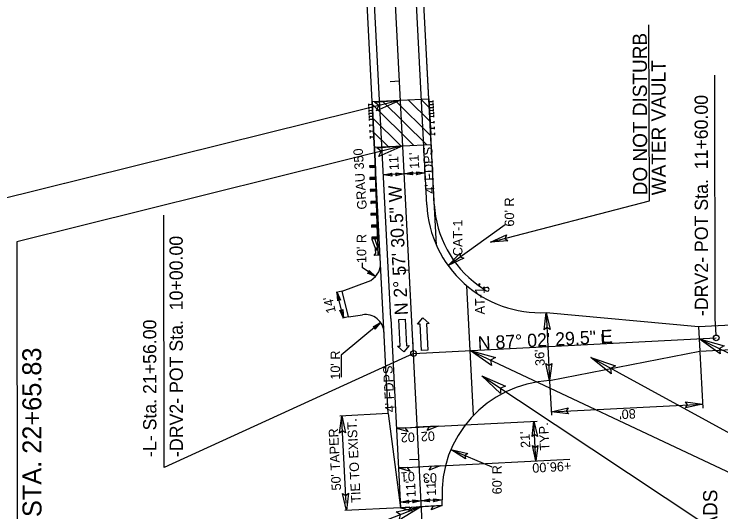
# Model space of a CAD drawing. Extents: x 1373164 to 1374172, y 550391 to 553180.
# Drawn here: x 1373512.6 to 1373885.8, y 551435.1 to 551698 of the extents above; entities that cross this region are included whole.
import ezdxf

# ---------------------------------------------------------------- set-up
doc = ezdxf.new("R2010")
doc.units = 0
for name, color, linetype in [('Default Symbol Cogo Elevation', 7, 'Continuous'), ('Exist Building Cogo Elevation', 7, 'Continuous'), ('Exist Building Cogo Number', 7, 'Continuous'), ('Exist Building Cogo Point CELL', 7, 'Continuous'), ('Exist Other Culture Fence Line Cogo Comment', 7, 'Continuous'), ('Exist Other Culture Fence Line Cogo Elevation', 7, 'Continuous'), ('Exist Other Culture Fence Line Cogo Point CELL', 7, 'Continuous'), ('Exist Other Culture Gate Cogo Comment', 7, 'Continuous'), ('Exist Other Culture Gate Cogo Elevation', 7, 'Continuous'), ('Exist Other Culture Gate Cogo Number', 7, 'Continuous'), ('Exist Other Culture Gate Cogo Point CELL', 7, 'Continuous'), ('Exist Roads EOP Other Cogo Comment', 7, 'Continuous'), ('Exist Roads EOP Other Cogo Elevation', 7, 'Continuous'), ('Exist Structure Major Deck Tunnel Box Culvert Cogo Number', 7, 'Continuous'), ('Exist Structure Major Deck Tunnel Box Culvert Cogo Point CELL', 7, 'Continuous'), ('Exist Structure Minor Pipes RCP 18 Inch Cogo Comment', 7, 'Continuous'), ('Exist Structure Minor Pipes RCP 18 Inch Cogo Number', 7, 'Continuous'), ('Exist Utilities Sanitary Sewer Manhole Cogo Elevation', 7, 'Continuous'), ('Exist Utilities Sanitary Sewer Manhole Cogo Number', 7, 'Continuous')]:
    doc.layers.add(name, color=color, linetype=linetype)

msp = doc.modelspace()

# ---------------------------------------------------------------- linework, layer by layer
at = {"layer": 'Default Symbol Cogo Elevation'}
for p, q in [((1373711.58, 551537.14), (1373696.04, 551837.8)), ((1373730.5, 551597.19), (1373718.01, 551838.94)), ((1373685.75, 551551.68), (1373699.49, 551556.7)), ((1373755.27, 551486.13), (1373751.74, 551554.43)), ((1373689.13, 551538.17), (1373685.75, 551551.68)), ((1373689.14, 551538.16), (1373696.54, 551539.22)), ((1373793.52, 551540.37), (1373874.01, 551533.02)), ((1373711.58, 551537.14), (1373716.7, 551437.27)), ((1373874.01, 551533.02), (1373874.68, 551520.03)), ((1373795.38, 551504.42), (1373874.68, 551520.03)), ((1373716.7, 551437.27), (1373727.72, 551437.84)), ((1373727.72, 551437.84), (1373738.71, 551438.41)), ((1373738.71, 551438.41), (1373738.56, 551441.4))]:
    msp.add_line(p, q, dxfattribs=at)
for centre, radius, start, end in [((1373790.42, 551600.29), 60, 182.9585, 272.9585), ((1373696.06, 551566.09), 10, 290.0644, 2.9585), ((1373697.96, 551529.32), 10, 2.9585, 98.1594), ((1373798.48, 551444.5), 60, 92.9585, 182.9585)]:
    msp.add_arc(centre, radius, start, end, dxfattribs=at)
at = {"layer": 'Exist Building Cogo Elevation'}
for p, q in [((1373702.62, 551633.05), (1373701.65, 551651.78)), ((1373732.58, 551634.6), (1373731.61, 551653.33)), ((1373703.26, 551620.57), (1373702.62, 551633.05)), ((1373733.22, 551622.12), (1373732.58, 551634.6)), ((1373704.84, 551570.58), (1373703.26, 551620.57))]:
    msp.add_line(p, q, dxfattribs=at)
at = {"layer": 'Exist Building Cogo Number'}
for p, q in [((1373710.16, 551487), (1373692.04, 551837.6)), ((1373735.61, 551575.89), (1373722, 551839.14)), ((1373710.16, 551487), (1373716.7, 551437.27))]:
    msp.add_line(p, q, dxfattribs=at)
at = {"layer": 'Exist Building Cogo Point CELL'}
for p, q in [((1373716.11, 551662.54), (1373711.12, 551662.28)), ((1373721.27, 551562.67), (1373716.28, 551562.41)), ((1373823.41, 551523.89), (1373823.15, 551528.89)), ((1373726.43, 551462.81), (1373721.44, 551462.55))]:
    msp.add_line(p, q, dxfattribs=at)
at = {"layer": 'Exist Other Culture Fence Line Cogo Comment'}
for p, q in [((1373702.9, 551627.64), (1373701.65, 551651.78)), ((1373730.28, 551629.06), (1373707.15, 551652.06)), ((1373732.62, 551633.79), (1373713.89, 551652.41)), ((1373732.23, 551641.22), (1373720.63, 551652.76)), ((1373731.85, 551648.65), (1373727.37, 551653.11)), ((1373732.86, 551629.19), (1373731.61, 551653.33)), ((1373723.54, 551628.71), (1373701.72, 551650.41)), ((1373716.8, 551628.36), (1373702.1, 551642.98)), ((1373710.06, 551628.01), (1373702.49, 551635.55)), ((1373702.9, 551627.64), (1373732.86, 551629.19)), ((1373703.32, 551627.66), (1373702.87, 551628.11))]:
    msp.add_line(p, q, dxfattribs=at)
at = {"layer": 'Exist Other Culture Fence Line Cogo Elevation'}
for p, q in [((1373701.65, 551651.78), (1373695.3, 551774.61)), ((1373731.61, 551653.33), (1373725.26, 551776.16)), ((1373701.65, 551651.78), (1373731.61, 551653.33))]:
    msp.add_line(p, q, dxfattribs=at)
at = {"layer": 'Exist Other Culture Fence Line Cogo Point CELL'}
for p, q in [((1373714.57, 551479.22), (1373726.56, 551479.83)), ((1373736.54, 551480.35), (1373724.56, 551479.73)), ((1373715.7, 551458.25), (1373726.64, 551458.81)), ((1373737.63, 551459.38), (1373725.64, 551458.76)), ((1373716.7, 551437.27), (1373728.68, 551437.89)), ((1373738.71, 551438.41), (1373726.73, 551437.79))]:
    msp.add_line(p, q, dxfattribs=at)
for points in [[(1373714.57, 551479.22), (1373720.67, 551477.53), (1373719.19, 551479.45)], [(1373736.54, 551480.35), (1373730.65, 551478.04), (1373731.92, 551480.11)], [(1373715.7, 551458.25), (1373721.8, 551456.56), (1373720.32, 551458.48)], [(1373737.63, 551459.38), (1373731.74, 551457.07), (1373733.01, 551459.14)], [(1373738.71, 551438.41), (1373732.82, 551436.1), (1373734.09, 551438.17)], [(1373716.7, 551437.27), (1373722.79, 551435.58), (1373721.31, 551437.51)]]:
    msp.add_lwpolyline(points, close=True, dxfattribs=at)
at = {"layer": 'Exist Other Culture Gate Cogo Comment'}
for p, q in [((1373703.34, 551618.03), (1373700.34, 551617.93)), ((1373701.87, 551616.98), (1373700.34, 551617.93)), ((1373700.34, 551617.93), (1373700.37, 551616.93)), ((1373700.37, 551616.93), (1373701.84, 551617.98)), ((1373703.37, 551617.03), (1373700.37, 551616.93)), ((1373701.84, 551617.98), (1373701.87, 551616.98)), ((1373701.84, 551617.98), (1373703.37, 551617.03)), ((1373701.87, 551616.98), (1373703.34, 551618.03)), ((1373703.37, 551617.03), (1373701.87, 551616.98)), ((1373703.26, 551620.57), (1373704.74, 551573.84)), ((1373703.34, 551618.03), (1373703.37, 551617.03)), ((1373703.54, 551611.73), (1373700.49, 551611.63)), ((1373702.05, 551610.68), (1373700.49, 551611.63)), ((1373700.49, 551611.63), (1373700.52, 551610.63)), ((1373700.52, 551610.63), (1373702.02, 551611.68)), ((1373703.57, 551610.73), (1373700.52, 551610.63)), ((1373702.02, 551611.68), (1373702.05, 551610.68)), ((1373702.02, 551611.68), (1373703.57, 551610.73)), ((1373703.54, 551611.73), (1373702.05, 551610.68)), ((1373703.74, 551605.43), (1373700.69, 551605.34)), ((1373702.25, 551604.38), (1373700.69, 551605.34)), ((1373700.69, 551605.34), (1373700.73, 551604.34)), ((1373700.73, 551604.34), (1373702.22, 551605.38)), ((1373703.77, 551604.43), (1373700.73, 551604.34)), ((1373702.22, 551605.38), (1373702.25, 551604.38)), ((1373702.22, 551605.38), (1373703.77, 551604.43)), ((1373703.74, 551605.43), (1373702.25, 551604.38)), ((1373703.94, 551599.13), (1373700.91, 551599.04)), ((1373702.45, 551598.09), (1373700.91, 551599.04)), ((1373700.91, 551599.04), (1373700.94, 551598.04)), ((1373700.94, 551598.04), (1373702.42, 551599.09)), ((1373702.42, 551599.09), (1373702.45, 551598.09)), ((1373702.42, 551599.09), (1373703.97, 551598.13)), ((1373703.94, 551599.13), (1373702.45, 551598.09)), ((1373703.94, 551599.13), (1373703.97, 551598.13)), ((1373703.97, 551598.13), (1373700.94, 551598.04)), ((1373704.14, 551592.84), (1373701, 551592.74)), ((1373702.6, 551591.79), (1373701, 551592.74)), ((1373701, 551592.74), (1373701.03, 551591.74)), ((1373701.03, 551591.74), (1373702.57, 551592.79)), ((1373704.17, 551591.84), (1373701.03, 551591.74)), ((1373702.57, 551592.79), (1373702.6, 551591.79)), ((1373702.57, 551592.79), (1373704.17, 551591.84)), ((1373704.14, 551592.84), (1373702.6, 551591.79)), ((1373704.34, 551586.54), (1373701.34, 551586.44)), ((1373702.87, 551585.49), (1373701.34, 551586.44)), ((1373701.34, 551586.44), (1373701.37, 551585.44)), ((1373701.37, 551585.44), (1373702.84, 551586.49)), ((1373704.37, 551585.54), (1373701.37, 551585.44)), ((1373702.84, 551586.49), (1373702.87, 551585.49)), ((1373702.84, 551586.49), (1373704.37, 551585.54)), ((1373704.34, 551586.54), (1373702.87, 551585.49)), ((1373704.54, 551580.24), (1373701.48, 551580.14)), ((1373703.04, 551579.19), (1373701.48, 551580.14)), ((1373701.48, 551580.14), (1373701.51, 551579.14)), ((1373701.51, 551579.14), (1373703.01, 551580.19)), ((1373703.01, 551580.19), (1373703.04, 551579.19)), ((1373703.01, 551580.19), (1373704.57, 551579.24)), ((1373704.54, 551580.24), (1373703.04, 551579.19)), ((1373704.57, 551579.24), (1373701.51, 551579.14)), ((1373701.51, 551579.14), (1373703.22, 551574.29)), ((1373703.04, 551579.19), (1373704.72, 551574.34)), ((1373704.72, 551574.34), (1373703.22, 551574.29)), ((1373703.22, 551574.29), (1373703.24, 551573.79)), ((1373704.76, 551573.34), (1373703.22, 551574.29)), ((1373703.22, 551574.29), (1373703.26, 551573.29)), ((1373703.26, 551573.29), (1373704.72, 551574.34)), ((1373704.76, 551573.34), (1373703.26, 551573.29)), ((1373703.44, 551573.75), (1373704.06, 551573.78)), ((1373703.55, 551571.7), (1373703.44, 551573.75)), ((1373704.06, 551573.78), (1373704.67, 551573.81)), ((1373704.67, 551573.81), (1373704.77, 551571.76)), ((1373702.75, 551570.48), (1373703.55, 551571.7)), ((1373705.69, 551570.63), (1373702.75, 551570.48)), ((1373704.77, 551571.76), (1373705.69, 551570.63)), ((1373758.11, 551555.54), (1373757.64, 551554.89)), ((1373757.64, 551554.89), (1373758.68, 551555.13)), ((1373757.64, 551554.89), (1373760.51, 551552.81)), ((1373757.64, 551554.89), (1373758.21, 551554.48)), ((1373758.68, 551555.13), (1373758.11, 551555.54)), ((1373758.21, 551554.48), (1373758.11, 551555.54)), ((1373758.21, 551554.48), (1373758.68, 551555.13)), ((1373760.58, 551553.76), (1373760.1, 551553.1)), ((1373761.14, 551553.35), (1373760.58, 551553.76)), ((1373760.67, 551552.69), (1373760.58, 551553.76)), ((1373762.19, 551553.55), (1373761.03, 551553.19)), ((1373760.1, 551553.1), (1373761.14, 551553.35)), ((1373760.1, 551553.1), (1373760.67, 551552.69)), ((1373760.56, 551552.77), (1373760.45, 551552.85)), ((1373760.56, 551552.77), (1373760.45, 551552.85)), ((1373760.51, 551552.81), (1373761.9, 551551.8)), ((1373760.67, 551552.69), (1373761.14, 551553.35)), ((1373760.67, 551552.69), (1373760.88, 551552.98)), ((1373760.67, 551552.69), (1373760.88, 551552.98))]:
    msp.add_line(p, q, dxfattribs=at)
msp.add_ellipse((1373762.48, 551552.61), major_axis=(0.583, 0.804), ratio=0.995379, start_param=3.141593, end_param=7.214552, dxfattribs=at)
at = {"layer": 'Exist Other Culture Gate Cogo Elevation'}
for p, q in [((1373699.7, 551650.69), (1373699.76, 551649.54)), ((1373701.65, 551651.78), (1373702.62, 551633.05)), ((1373731.61, 551653.33), (1373732.58, 551634.6)), ((1373731.69, 551651.77), (1373733.69, 551651.87)), ((1373733.66, 551652.44), (1373733.72, 551651.3)), ((1373733.74, 551650.88), (1373733.8, 551649.74)), ((1373701.73, 551650.22), (1373699.73, 551650.11)), ((1373699.78, 551649.13), (1373699.84, 551647.98)), ((1373701.81, 551648.66), (1373699.81, 551648.55)), ((1373699.86, 551647.57), (1373699.92, 551646.42)), ((1373701.89, 551647.1), (1373699.89, 551646.99)), ((1373731.77, 551650.21), (1373733.77, 551650.31)), ((1373731.85, 551648.65), (1373733.85, 551648.75)), ((1373731.93, 551647.08), (1373733.93, 551647.19)), ((1373733.82, 551649.32), (1373733.88, 551648.18)), ((1373733.9, 551647.76), (1373733.96, 551646.62)), ((1373699.94, 551646.01), (1373700, 551644.86)), ((1373701.97, 551645.54), (1373699.97, 551645.43)), ((1373700.02, 551644.44), (1373700.08, 551643.3)), ((1373702.05, 551643.98), (1373700.05, 551643.87)), ((1373732.01, 551645.52), (1373734.01, 551645.63)), ((1373732.09, 551643.96), (1373734.09, 551644.07)), ((1373733.98, 551646.2), (1373734.04, 551645.06)), ((1373734.06, 551644.64), (1373734.12, 551643.5)), ((1373700.11, 551642.88), (1373700.16, 551641.74)), ((1373702.13, 551642.42), (1373700.13, 551642.31)), ((1373700.27, 551639.76), (1373700.33, 551638.62)), ((1373732.25, 551640.84), (1373734.25, 551640.95)), ((1373734.22, 551641.52), (1373734.28, 551640.37)), ((1373702.29, 551639.29), (1373700.3, 551639.19)), ((1373700.43, 551636.64), (1373700.49, 551635.5)), ((1373702.45, 551636.17), (1373700.46, 551636.07)), ((1373732.41, 551637.72), (1373734.41, 551637.83)), ((1373734.38, 551638.4), (1373734.44, 551637.25)), ((1373700.59, 551633.52), (1373700.65, 551632.38)), ((1373702.62, 551633.05), (1373700.62, 551632.95)), ((1373732.58, 551634.6), (1373734.57, 551634.7)), ((1373734.54, 551635.28), (1373734.6, 551634.13))]:
    msp.add_line(p, q, dxfattribs=at)
at = {"layer": 'Exist Other Culture Gate Cogo Number'}
for p, q in [((1373702.62, 551633.05), (1373703.26, 551620.57)), ((1373734.5, 551597.4), (1373732.58, 551634.6))]:
    msp.add_line(p, q, dxfattribs=at)
msp.add_arc((1373790.42, 551600.29), 56, 182.9585, 234.1663, dxfattribs=at)
at = {"layer": 'Exist Other Culture Gate Cogo Point CELL'}
msp.add_line((1373714.57, 551479.22), (1373736.54, 551480.35), dxfattribs=at)
at = {"layer": 'Exist Roads EOP Other Cogo Elevation'}
for p, q in [((1373734.13, 551313.82), (1373707.02, 551838.37)), ((1373723.54, 551518.73), (1373883.33, 551526.99))]:
    msp.add_line(p, q, dxfattribs=at)
at = {"layer": 'Exist Structure Major Deck Tunnel Box Culvert Cogo Point CELL'}
for points in [[(1373702.97, 551651.56), (1373716.63, 551652.55), (1373704.03, 551646.95), (1373705.13, 551649.7)], [(1373704.21, 551627.42), (1373717.88, 551628.41), (1373705.28, 551622.81), (1373706.37, 551625.56)], [(1373712.17, 551612.49), (1373707.63, 551613.04), (1373712.11, 551614.07), (1373711.58, 551613.24)], [(1373714.11, 551614.15), (1373718.64, 551613.61), (1373714.16, 551612.57), (1373714.7, 551613.4)], [(1373723.17, 551613.06), (1373718.64, 551613.61), (1373723.12, 551614.64), (1373722.59, 551613.81)], [(1373725.09, 551614.71), (1373729.63, 551614.17), (1373725.15, 551613.14), (1373725.68, 551613.97)], [(1373773.28, 551578.28), (1373764.18, 551577.52), (1373772.54, 551581.34), (1373771.83, 551579.51)], [(1373750, 551569.16), (1373741.79, 551565.15), (1373748.19, 551571.74), (1373748.2, 551569.77)], [(1373700.18, 551562.55), (1373703.51, 551559.42), (1373699.3, 551561.25), (1373700.22, 551561.6)], [(1373683.47, 551546.47), (1373683.13, 551551.02), (1373685, 551546.83), (1373684.08, 551547.19)], [(1373686.18, 551542), (1373686.52, 551537.44), (1373684.65, 551541.64), (1373685.56, 551541.27)], [(1373792.44, 551531.3), (1373793.52, 551540.37), (1373795.59, 551531.42), (1373793.93, 551532.48)], [(1373702.13, 551532.82), (1373706.09, 551535.09), (1373703.11, 551531.59), (1373703.04, 551532.57)], [(1373885.47, 551518.53), (1373874.34, 551526.52), (1373887.6, 551522.75), (1373885, 551521.34)], [(1373764.72, 551512.42), (1373753.5, 551520.28), (1373766.81, 551516.66), (1373764.22, 551515.22)], [(1373827.85, 551508.02), (1373817.12, 551516.54), (1373830.18, 551512.13), (1373827.52, 551510.85)], [(1373796.46, 551513.49), (1373795.38, 551504.42), (1373793.31, 551513.37), (1373794.97, 551512.31)], [(1373769.46, 551497.57), (1373759.5, 551506.97), (1373772.14, 551501.46), (1373769.37, 551500.42)], [(1373867.06, 551493.12), (1373876.13, 551492.03), (1373867.17, 551489.97), (1373868.24, 551491.63)], [(1373805.3, 551486.82), (1373796.23, 551487.9), (1373805.19, 551489.97), (1373804.12, 551488.31)], [(1373684.5, 551476.66), (1373685.59, 551485.73), (1373687.65, 551476.77), (1373685.99, 551477.84)], [(1373786.13, 551474.8), (1373787.1, 551482.96), (1373788.96, 551474.9), (1373787.47, 551475.86)], [(1373750.94, 551463.04), (1373743.27, 551467.99), (1373752.22, 551465.92), (1373750.53, 551464.9)], [(1373789.16, 551470.15), (1373788.18, 551461.99), (1373786.33, 551470.05), (1373787.82, 551469.09)], [(1373689.25, 551444.86), (1373688.17, 551435.79), (1373686.1, 551444.75), (1373687.76, 551443.68)], [(1373732.1, 551440.29), (1373727.57, 551440.83), (1373732.05, 551441.87), (1373731.51, 551441.04)], [(1373734.02, 551441.94), (1373738.56, 551441.4), (1373734.08, 551440.37), (1373734.61, 551441.2)], [(1373714.3, 551435.1), (1373727.72, 551437.84), (1373715.95, 551430.67), (1373716.68, 551433.54)], [(1373714.3, 551435.1), (1373727.72, 551437.84), (1373715.95, 551430.67), (1373716.68, 551433.54)], [(1373721.1, 551439.72), (1373716.56, 551440.27), (1373721.04, 551441.3), (1373720.51, 551440.47)], [(1373723.04, 551441.38), (1373727.57, 551440.83), (1373723.09, 551439.8), (1373723.63, 551440.63)]]:
    msp.add_lwpolyline(points, close=True, dxfattribs=at)
at = {"layer": 'Exist Structure Minor Pipes RCP 18 Inch Cogo Comment'}
msp.add_line((1373723.54, 551518.73), (1373723.13, 551526.72), dxfattribs=at)
at = {"layer": 'Exist Structure Minor Pipes RCP 18 Inch Cogo Number'}
for p, q in [((1373882.81, 551537.15), (1373882.69, 551665.81)), ((1373591.78, 551458.5), (1373591.66, 551591.83)), ((1373883.25, 551528.49), (1373882.81, 551537.15)), ((1373723.54, 551518.73), (1373591.78, 551458.5))]:
    msp.add_line(p, q, dxfattribs=at)
for centre in [(1373883.33, 551526.99), (1373723.54, 551518.73)]:
    msp.add_circle(centre, 1.5, dxfattribs=at)
at = {"layer": 'Exist Utilities Sanitary Sewer Manhole Cogo Elevation'}
for p, q in [((1373848.06, 551599.35), (1373847.8, 551692.32)), ((1373716.63, 551652.55), (1373462.35, 551589.41)), ((1373717.88, 551628.41), (1373514.04, 551577.79)), ((1373718.64, 551613.61), (1373707.63, 551613.04)), ((1373729.63, 551614.17), (1373718.64, 551613.61)), ((1373764.18, 551577.52), (1373848.06, 551599.35)), ((1373741.79, 551565.15), (1373771.83, 551586.85)), ((1373514.04, 551577.79), (1373514.31, 551412.47)), ((1373696.39, 551566.54), (1373696.39, 551564.13)), ((1373703.51, 551559.42), (1373696.39, 551564.13)), ((1373685.75, 551551.68), (1373682.64, 551550.9)), ((1373686.52, 551537.44), (1373683.13, 551551.02)), ((1373793.52, 551540.37), (1373795.38, 551504.42)), ((1373706.09, 551535.09), (1373685.31, 551517.89)), ((1373689.13, 551538.17), (1373686.02, 551537.4)), ((1373874.01, 551533.02), (1373897.27, 551534.22)), ((1373874.34, 551526.52), (1373967.64, 551481.15)), ((1373753.5, 551520.28), (1373911.56, 551445.73)), ((1373874.68, 551520.03), (1373897.94, 551521.24)), ((1373685.31, 551517.89), (1373685.32, 551506.3)), ((1373939.11, 551449.88), (1373817.12, 551516.54)), ((1373874.71, 551519.47), (1373876.24, 551489.78)), ((1373759.5, 551506.97), (1373875.68, 551429.81)), ((1373795.39, 551504.17), (1373796.32, 551486.17)), ((1373796.23, 551487.9), (1373876.13, 551492.03)), ((1373710.16, 551487), (1373684.59, 551485.68)), ((1373687.97, 551439.62), (1373685.68, 551483.82)), ((1373736.54, 551480.35), (1373788.77, 551483.05)), ((1373788.18, 551461.99), (1373787.1, 551482.96)), ((1373743.27, 551467.99), (1373764.82, 551458.82)), ((1373737.63, 551459.38), (1373806.02, 551462.91)), ((1373727.57, 551440.83), (1373716.56, 551440.27)), ((1373738.56, 551441.4), (1373727.57, 551440.83)), ((1373716.7, 551437.27), (1373687.17, 551435.74))]:
    msp.add_line(p, q, dxfattribs=at)
msp.add_lwpolyline([(1373727.72, 551437.84), (1373383.63, 551303.77), (1373383.35, 551567.48)], dxfattribs=at)
at = {"layer": 'Exist Utilities Sanitary Sewer Manhole Cogo Number'}
for p, q in [((1373715.74, 551536.62), (1373719.04, 551536.79)), ((1373716.47, 551522.64), (1373715.74, 551536.62)), ((1373719.04, 551536.79), (1373719.76, 551522.81)), ((1373725.54, 551534.18), (1373728.48, 551537.48)), ((1373728.48, 551537.48), (1373731.84, 551534.5)), ((1373727.04, 551534.25), (1373725.54, 551534.18)), ((1373727.76, 551520.27), (1373727.04, 551534.25)), ((1373731.84, 551534.5), (1373730.34, 551534.42)), ((1373730.34, 551534.42), (1373731.06, 551520.44)), ((1373714.97, 551522.56), (1373716.47, 551522.64)), ((1373718.33, 551519.58), (1373714.97, 551522.56)), ((1373721.26, 551522.89), (1373718.33, 551519.58)), ((1373719.76, 551522.81), (1373721.26, 551522.89)), ((1373731.06, 551520.44), (1373727.76, 551520.27))]:
    msp.add_line(p, q, dxfattribs=at)

# ---------------------------------------------------------------- texts
at = {"layer": 'Exist Other Culture Gate Cogo Comment'}
for s, rotation, p in [('GRAU 350', 93.9618, (1373698.89, 551594.95)), ('CAT-1', 90.0509, (1373749.36, 551570.16)), ('AT-1', 90.1567, (1373761.06, 551539.39))]:
    msp.add_text(s, height=5, rotation=rotation, dxfattribs=at).set_placement(p)
at = {"layer": 'Exist Other Culture Gate Cogo Point CELL'}
for s, p in [('02', (1373724.07, 551477.06)), ('02', (1373734.64, 551477.64)), ('01', (1373724.08, 551456.31)), ('03', (1373735.76, 551455.62))]:
    msp.add_text(s, height=5, rotation=182.9585, dxfattribs=at).set_placement(p)
at = {"layer": 'Exist Roads EOP Other Cogo Comment'}
for s, rotation, p in [('N 2%%d 57\' 30.5" W', 92.9585, (1373720.66, 551539.12)), ('N 87%%d 02\' 29.5" E', 2.9585, (1373757.63, 551520.69))]:
    msp.add_text(s, height=7, rotation=rotation, dxfattribs=at).set_placement(p)
at = {"layer": 'Exist Structure Major Deck Tunnel Box Culvert Cogo Number'}
for s, rotation, p in [("14'", 103.8222, (1373682.58, 551540.68)), ('TIE TO EXIST.', 92.9585, (1373695.68, 551440.02)), ("50' TAPER", 92.9585, (1373685.33, 551446.49))]:
    msp.add_text(s, height=5, rotation=rotation, dxfattribs=at).set_placement(p)
at = {"layer": 'Exist Structure Minor Pipes RCP 18 Inch Cogo Number'}
for s, height, rotation, p in [('DO NOT DISTURB', 7.5, 90.1567, (1373846.93, 551602.29)), ('WATER VAULT', 7.5, 90.1567, (1373856.76, 551602.32)), ('-DRV2- POT Sta.  11+60.00', 7, 90.0509, (1373879.02, 551538.52)), ('-DRV2- POT Sta.  10+00.00', 7, 90.0509, (1373601.76, 551464.07)), ('-L- Sta. 21+56.00', 7, 90.0509, (1373587.76, 551464.06)), ('-L- STA. 22+65.83', 10, 90.095, (1373527.11, 551412.26)), ('FORCE MAIN, NO LOADS', 7.5, 90.1567, (1373884.23, 551326.47))]:
    msp.add_text(s, height=height, rotation=rotation, dxfattribs=at).set_placement(p)
at = {"layer": 'Exist Utilities Sanitary Sewer Manhole Cogo Elevation'}
for s, rotation, p in [("11'", 92.9585, (1373726.57, 551616.4)), ("4' FDPS", 92.9585, (1373734.67, 551603.29)), ("11'", 92.9585, (1373715.81, 551615.68)), ("60' R", 90.1567, (1373776.64, 551585.78)), ("10' R", 90.1567, (1373698.57, 551566.47)), ("10' R", 90.1567, (1373684.72, 551504.9)), ("36'", 92.9585, (1373792.88, 551512.29)), ("4' FDPS", 92.9585, (1373713.67, 551487.8)), ("80'", 182.9585, (1373840.71, 551489.44)), ('TYP.', 92.9585, (1373795.29, 551467.62)), ("21'", 92.9585, (1373785.2, 551469)), ('+96.00', 182.9585, (1373806.7, 551461.77)), ("60' R", 90.1567, (1373770.1, 551444.34)), ("11'", 92.9585, (1373724.74, 551442.91)), ("11'", 92.9585, (1373735.5, 551443.63))]:
    msp.add_text(s, height=5, rotation=rotation, dxfattribs=at).set_placement(p)

doc.saveas('drawing.dxf')
